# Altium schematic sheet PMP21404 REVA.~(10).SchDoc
size 431 x 279 mm; Date: Not shown in title block; ApprovedBy: Not shown in title block; CheckedBy: Not shown in title block; Author: Not shown in title block; CompanyName: Not shown in title block; Engineer: Not shown in title block; Organization: Not shown in title block; Address1: Not shown in title block; Address2: Not shown in title block; Address3: Not shown in title block; Address4: Not shown in title block; DocumentNumber: 1; Revision: Use project parameter SCH_Rev; SheetNumber: 1; SheetTotal: 1; PageSetup: Record=PageOptions¦CenterHorizontal=True¦CenterVertical=True¦PrintScale=1.00¦XCorrection=1.00¦YCorrection=1.00¦PrintKind=0¦BorderSize=5000000¦LeftOffset=0¦BottomOffset=0¦Orientation=2¦PaperLength=1000¦PaperWidth=1000¦Scale=100¦PaperSource=15¦PrintQuality=600¦MediaType=1¦DitherType=10¦PaperKind=Letter¦PrintScaleMode=1
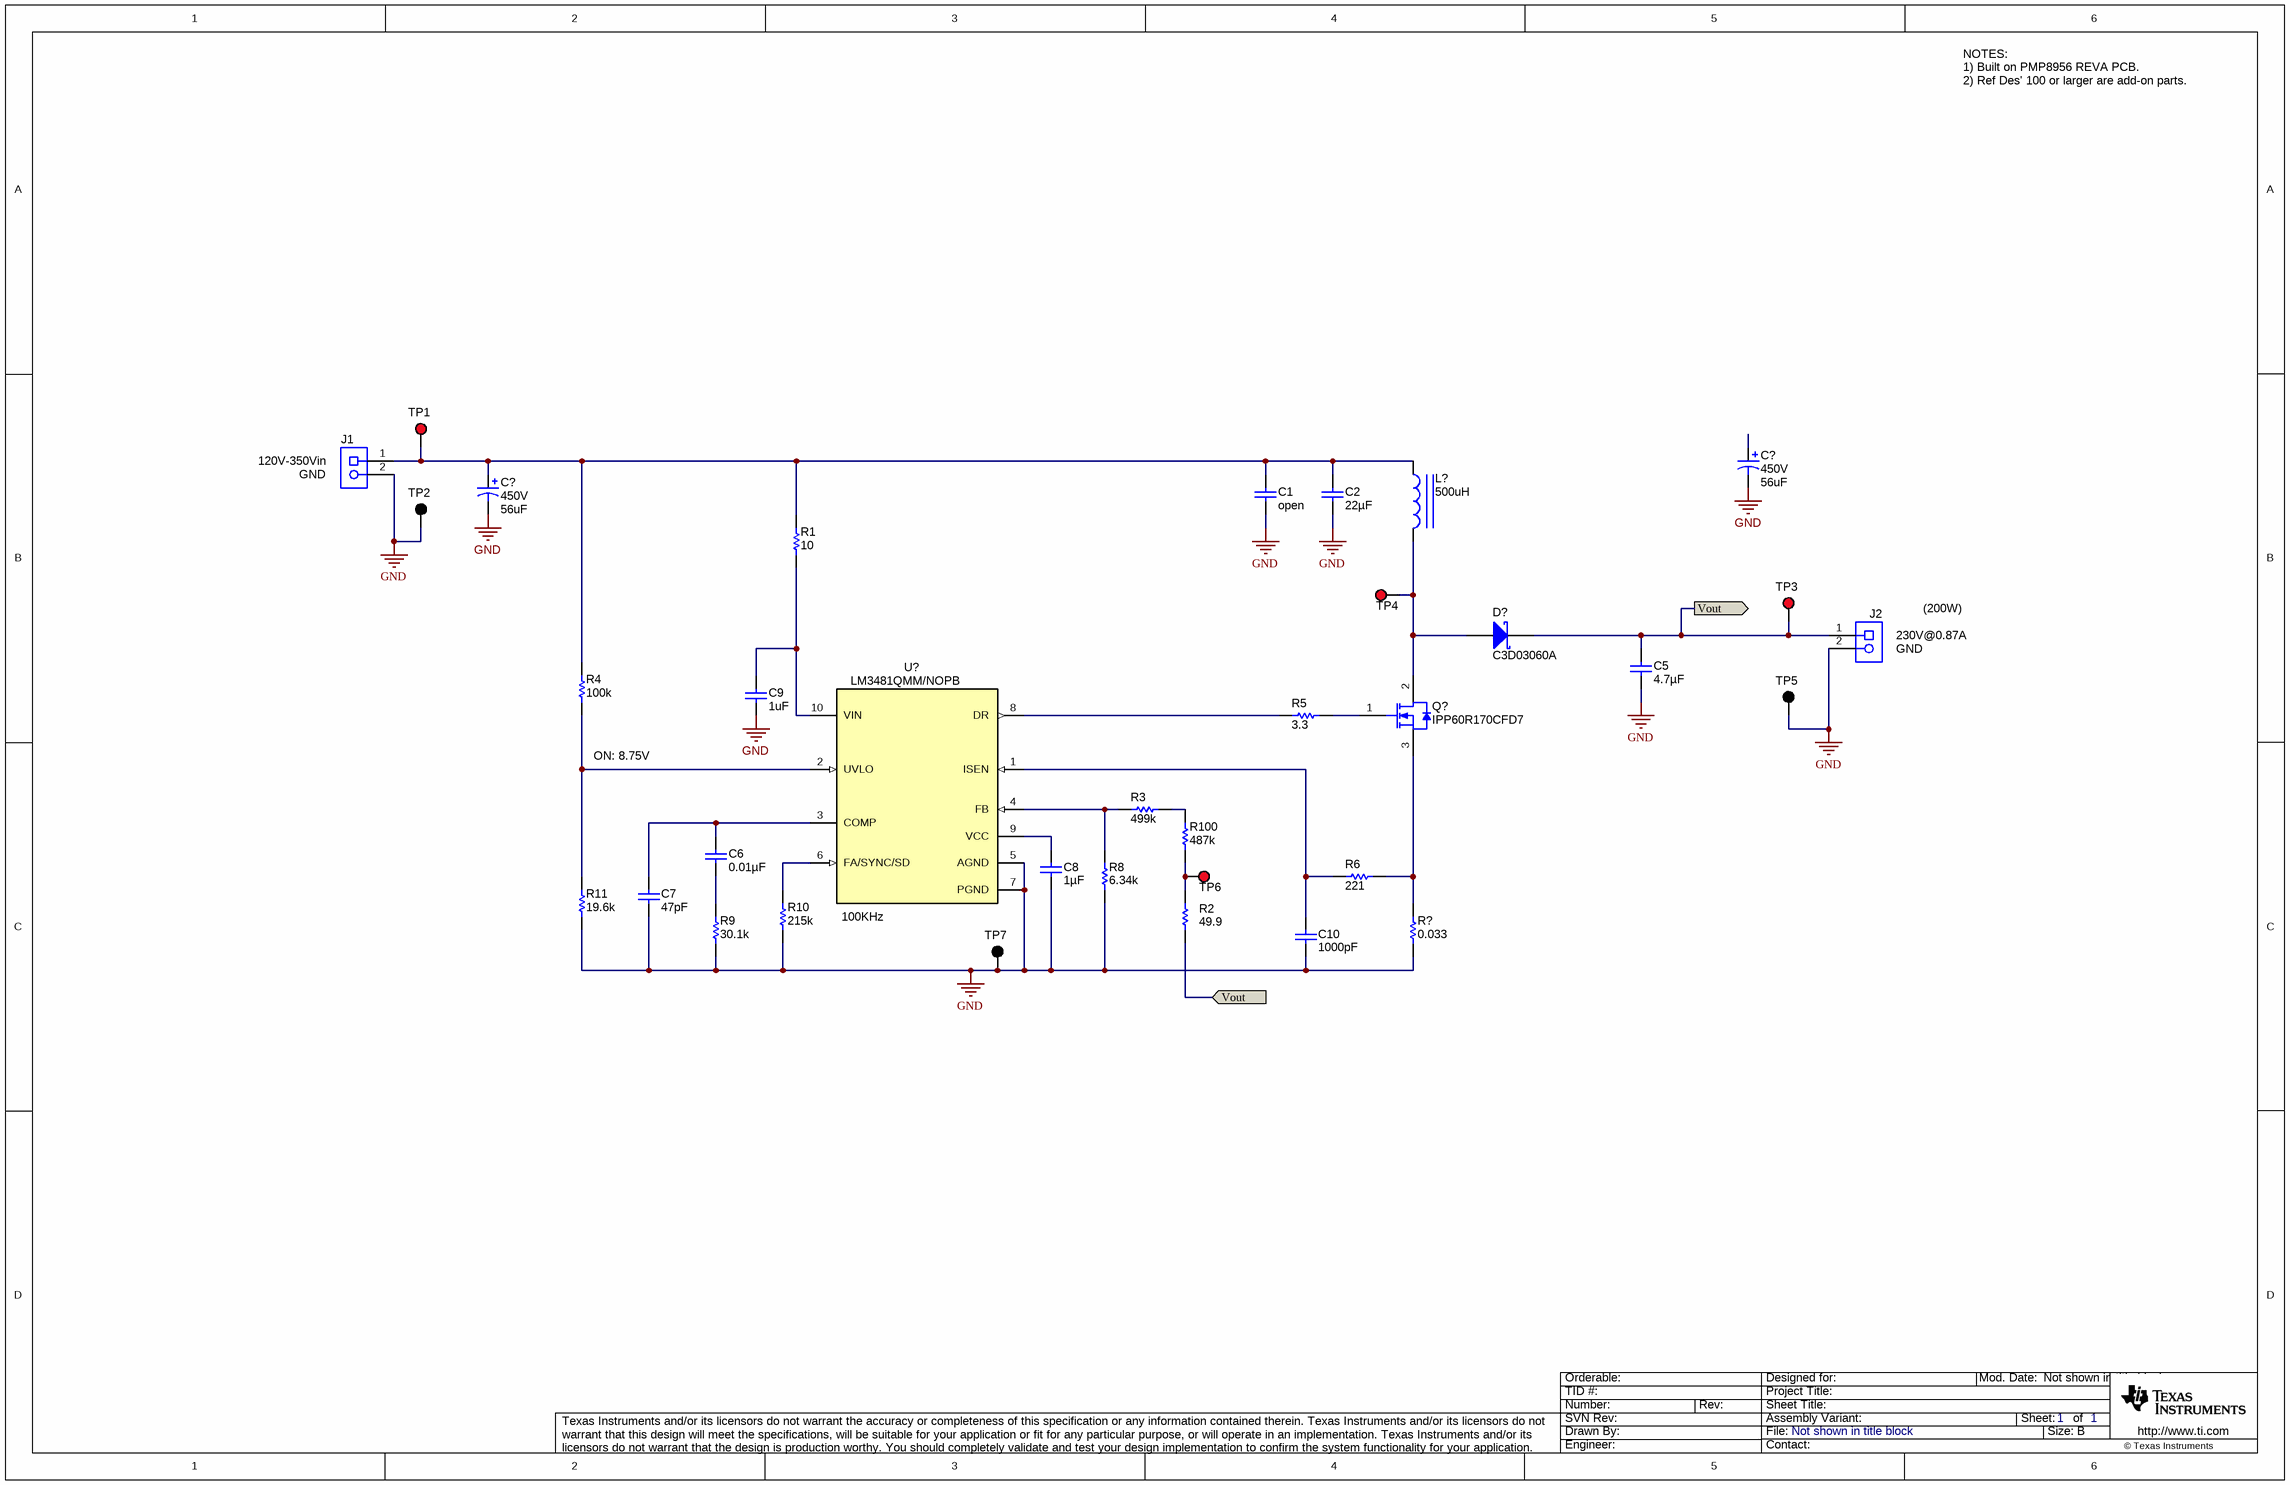
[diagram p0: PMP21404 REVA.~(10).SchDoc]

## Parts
(Parts that share a designator on the sheet are numbered #1, #2 ... from top to bottom, then left to right.)
C1  ValueDisplayed: open  [1206L]
C2  ValueDisplayed: 22µF  [1210]  (hidden comment: GRM32ER71E226ME15)
C5  ValueDisplayed: 4.7µF  [1210]  (hidden comment: C3225X7S2A475M)
C6  ValueDisplayed: 0.01µF  [0603]  (hidden comment: C1608X7R1H103K)
C7  ValueDisplayed: 47pF  [0603]  (hidden comment: C1608C0G1H470J)
C8  ValueDisplayed: 1µF  [0603L]  (hidden comment: C1608X7R1C105K)
C9  ValueDisplayed: 1uF  [0805L]  (hidden comment: Capacitor)
C10  ValueDisplayed: 1000pF  [0603L]  (hidden comment: C1608X7R1H102K)
C?#1  VDC_V: 450V  ValueDisplayed: 56uF  [Nichicon_2000x2500_Snap]  (hidden comment: LLS2W560MELY)
C?#2  VDC_V: 450V  ValueDisplayed: 56uF  [Nichicon_2000x2500_Snap]  (hidden comment: LLS2W560MELY)
D?  C3D03060A  [TO-220-2]
J1  Receptacle_2x1  [TERM_BLK_ED555-2DS]  (value not drawn)
J2  Receptacle_2x1  [TERM_BLK_ED555-2DS]  (value not drawn)
L?  ValueDisplayed: 500uH  [5717-RC]  (hidden comment: 5717-RC)
Q?  IPP60R170CFD7  [TO-220AB]
R1  value 10  [0603L]  (hidden comment: Resistor)
R2  value 49.9  [0603L]  (hidden comment: Resistor)
R3  ValueDisplayed: 499k  [0805_HV]  (hidden comment: Resistor)
R4  value 100k  [0603L]  (hidden comment: Resistor)
R5  ValueDisplayed: 3.3  [0603]  (hidden comment: Resistor)
R6  value 221  [0603L]  (hidden comment: Resistor)
R8  ValueDisplayed: 6.34k  [0603L]  (hidden comment: Resistor)
R9  ValueDisplayed: 30.1k  [0603]  (hidden comment: Resistor)
R10  value 215k  [0603]  (hidden comment: Resistor)
R11  value 19.6k  [0603L]  (hidden comment: Resistor)
R100  ValueDisplayed: 487k  [0805_HV]  (hidden comment: Resistor)
R?  ValueDisplayed: 0.033  [1206]  (hidden comment: ERJ-8CWFR033V)
TP1  5000  [Keystone5000]  (value not drawn)
TP2  5001  [Keystone5001]  (value not drawn)
TP3  5000  [Keystone5000]  (value not drawn)
TP4  5000  [Keystone5000]  (value not drawn)
TP5  5001  [Keystone5001]  (value not drawn)
TP6  5000  [Keystone5000]  (value not drawn)
TP7  5001  [Keystone5001]  (value not drawn)
U?  LM3481QMM/NOPB  [DGS0010A_N]

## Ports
Vout

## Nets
GND: C1.2 C2.2 C5.2 C7.2 C8.2 C9.2 C10.2 C?#1.2(-) C?#2.2(-) J1.2 J2.2 R8.1 R9.1 R10.1 R11.1 R?.1 TP2.1 TP5.1 TP7.1 U?.5(AGND) U?.7(PGND)
Vout: C5.1 D?.1(K) J2.1 R2.1 TP3.1 ; port Vout
NetC1_1: C1.1 C2.1 C?#2.1(+) J1.1 L?.1 R1.2 R4.2 TP1.1
NetC6_1: C6.1 C7.1 U?.3(COMP)
NetC6_2: C6.2 R9.2
NetC8_1: C8.1 U?.9(VCC)
NetC9_1: C9.1 R1.1 U?.10(VIN)
NetC10_1: C10.1 R6.2 U?.1(ISEN)
NetD?_2: D?.2(A) L?.2 Q?.2(D) TP4.1
NetQ?_1: Q?.1(G) R5.2
NetQ?_3: Q?.3(S) R6.1 R?.2
NetR2_2: R2.2 R100.1 TP6.1
NetR3_1: R3.1 R8.2 U?.4(FB)
NetR3_2: R3.2 R100.2
NetR4_1: R4.1 R11.2 U?.2(UVLO)
NetR5_1: R5.1 U?.8(DR)
NetR10_2: R10.2 U?.6(FA/SYNC/SD)

Not connected (* = marked no-connect by the designer): C?#1 1(+)

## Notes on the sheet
- NOTES:
  1) Built on PMP8956 REVA PCB.
  2) Ref Des' 100 or larger are add-on parts.
- (near J1) 120V-350Vin
- (near J1) GND
- (near J2) 230V@0.87A
- (200W)
- (near J2) GND
- (near R4) ON: 8.75V
- (near U?) 100KHz

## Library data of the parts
C1 = C3216X7R2A104M: CAP, open, 1206; Polarized: N; CompType: Capacitor; U/M: EA; Cap_F: 0.0000001; Tolerance_%: 20; TaMin_C: -55; TaMax_C: 125
C2 = GRM32ER71E226KE15L: CAP, CERM, 22 µF, 25 V, +/- 10%, X7R, 1210; Manufacturer: MuRata; Polarized: N; CompType: Capacitor; Value: 22uF; U/M: EA; Cap_F: 0.000022; Tolerance_%: 10; Value1: Unknown; VDC_V: 25; Value2: 25V; TaMin_C: -55; TaMax_C: 125; AEC Category: Q200
C5 = C3225X5R1E106K: CAP, CERM, 4.7uF, 100V, +/-20%, X7S, 1210; Manufacturer: TDK; Polarized: N; CompType: Capacitor; U/M: EA; Cap_F: 0.00001; Tolerance_%: 20; ESR_Ohm: 0.015; Value1: 0.015 ohm; VDC_V: 100; IRMS_A: 3; TaMin_C: -55; TaMax_C: 125
C6 = C1608X7R1H103K: CAP, CERM, 0.01uF, 50V, +/-10%, X7R, 0603; Manufacturer: TDK; Polarized: N; CompType: Capacitor; U/M: EA; Cap_F: 0.00000001; Tolerance_%: 10; ESR_Ohm: 0.0539; Value1: 0.0539 ohm; VDC_V: 50; TaMin_C: -55; TaMax_C: 125
C7 = C1608C0G1H470J: CAP, CERM, 47pF, 50V, +/-5%, C0G/NP0, 0603; Manufacturer: TDK; Polarized: N; CompType: Capacitor; U/M: EA; Cap_F: 0.000000000047; Tolerance_%: 5; ESR_Ohm: 0.22; Value1: 0.22 ohm; VDC_V: 50; TaMin_C: -55; TaMax_C: 125
C8 = C1608X7R1C105K: CAP, CERM, 1uF, 16V, +/-10%, X7R, 0603; Manufacturer: TDK; Polarized: N; CompType: Capacitor; U/M: EA; Cap_F: 0.000001; Tolerance_%: 10; ESR_Ohm: 0.0057; Value1: 0.0057 ohm; VDC_V: 16; TaMin_C: -55; TaMax_C: 125; Cap_Case: 0603
C9 = CMP-0008350-2: CAP, CERM, 1 uF, 50 V, +/- 10%, X7R, 0805; PartNumber: GRM21BR71H105KA12L; Manufacturer: MuRata; Polarized: N; Value: 1uF; U/M: EA; Cap_F: 1µF; Value1: Unknown; VDC_V: 50V; TaMin_C: -55°C; TaMax_C: 125°C; Cap_Case: 0805; AEC Category: Q200; SizeArea_mm2: 2.5; SizeAreaWB_mm2: 6.75; SizeX_mm: 2; SizeY_mm: 1.25; SizeZ_mm: 1.45
C10 = C1608X7R1H102K: CAP, CERM, 1000pF, 50V, +/-10%, X7R, 0603; Manufacturer: TDK; Polarized: N; CompType: Capacitor; U/M: EA; Cap_F: 0.000000001; Tolerance_%: 10; ESR_Ohm: 0.24; Value1: 0.24 ohm; VDC_V: 50; TaMin_C: -55; TaMax_C: 125; Cap_Case: 0603
C?#1 C?#2 = CMP-0010119-2: CAP, AL, 56 uF, 450 V, +/- 20%, TH; Manufacturer: Nichicon; TaMin_C: -25°C; Polarized: Y; SizeAreaWB_mm2: 484; Value1: Unknown; U/M: EA; Value: 56uF; TaMax_C: 85°C; SizeZ_mm: 27; SizeX_mm: 20; Cap_Case: 20x25mm; SizeArea_mm2: 400; CompType: Capacitor; AEC Qualified: N; Cap_F: 56µF; IRMS_A: 6.1dA; AEC Category: Q200
D? = CMP-0079543-1: Diode, Schottky, 600 V, 11 A, AEC-Q101, TH; Manufacturer: Cree; SizeAreaWB_mm2: 77.630025; Vr_V: 600V; SizeArea_mm2: 44.650025; AEC Qualified: Y; TJmax_C: 175°C; AEC Category: Q101; Value: 600V; SizeZ_mm: 20; Green_REACh: Incomplete; Io_A: 11A; SizeY_mm: 4.445; Green_Lifecycle: Active; SizeX_mm: 10.045; RJC_CperW: 3.2
J1 J2 = CMP-0074913-1: Terminal Block, 3.5mm Pitch, 2x1, TH; PartNumber: ED555/2DS; Manufacturer: On-Shore Technology; Cert_CULUS: Y; CNHeader: False; ContactFinish: Brass; CT: True; Current_A: 6A; Gender: Female; Green_Lifecycle: Active; Green_REACh: Passed; Pitch_mm: 3.5; Row_Count: 1; Shrouded: N; Voltage_V: 150V
L? = CMP-0055726-1: Inductor, Toroid, Powdered Iron, 500 uH, 4 A, 0.15 ohm, TH; Manufacturer: Bourns; SizeAreaWB_mm2: 1008; DCR_ohm: 1.5d; Value: 500uH; Imax_A: 4A; SizeZ_mm: 46; SizeX_mm: 19; SizeArea_mm2: 874; Ind_H: 500µH; AEC Qualified: N; AEC Category: Q200
Q? = CMP-0001174-3: MOSFET, N-CH, 600 V, 51 A, TO-220AB; Alternate Manufacturer: None; Manufacturer: Infineon Technologies; SizeZ_mm: 19.4; ChType: N; Value2: 28 nC; VdsMax_V: 600V; SizeX_mm: 10.2; SizeY_mm: 4.5; Vgs_V: 20V; Value: 600V; SizeArea_mm2: 45.9; AEC Category: Q101; IdsMax_A: 51A; SizeAreaWB_mm2: 79.3; U/M: EA; QgTyp_nC: 28
R1 = CMP-0025703-4: RES, 10, 5%, 0.1 W, AEC-Q200 Grade 0, 0603; PartNumber: CRCW060310R0JNEA; Manufacturer: Vishay-Dale; Value_Code: 10R0; Power_W: 100mW; Value2: 0.1W; VDC_V: 75V; TempCo: 200 ppm/C; EIA_Code: E24; AEC Category: Q200; AEC Grade: 0; AEC Qualified: Y; SizeArea_mm2: 1.28; SizeX_mm: 1.6; SizeY_mm: 0.8; SizeZ_mm: 1
R2 = CMP-0022448-4: RES, 49.9, 1%, 0.1 W, AEC-Q200 Grade 0, 0603; PartNumber: CRCW060349R9FKEA; Manufacturer: Vishay-Dale; Value_Code: 49R9; Power_W: 100mW; Value2: 0.1W; VDC_V: 75V; TempCo: 100 ppm/C; EIA_Code: E96; AEC Category: Q200; AEC Grade: 0; AEC Qualified: Y; SizeArea_mm2: 1.28; SizeX_mm: 1.6; SizeY_mm: 0.8; SizeZ_mm: 1
R3 = CMP-0021281-3: RES, 499 k, 1%, 0.125 W, AEC-Q200 Grade 0, 0805; PartNumber: CRCW0805499KFKEA; Manufacturer: Vishay-Dale; Value: 499k; Power_W: 125mW; Value2: 0.125W; VDC_V: 150V; TempCo: 100 ppm/C; EIA_Code: E96; AEC Category: Q200; AEC Qualified: Y; AEC Grade: 0; SizeArea_mm2: 2.5; SizeX_mm: 2; SizeY_mm: 1.25; SizeZ_mm: 1.45
R4 = CMP-0021990-4: RES, 100 k, 1%, 0.1 W, AEC-Q200 Grade 0, 0603; PartNumber: CRCW0603100KFKEA; Manufacturer: Vishay-Dale; Power_W: 100mW; Value2: 0.1W; VDC_V: 75V; TempCo: 100 ppm/C; EIA_Code: E96; AEC Category: Q200; AEC Grade: 0; AEC Qualified: Y; SizeArea_mm2: 1.28; SizeX_mm: 1.6; SizeY_mm: 0.8; SizeZ_mm: 1
R5 = CMP-0025805-4: RES, 3.3, 5%, 0.1 W, AEC-Q200 Grade 0, 0603; PartNumber: CRCW06033R30JNEA; Manufacturer: Vishay-Dale; Value: 3.3; Value_Code: 3R30; Power_W: 100mW; Value2: 0.1W; VDC_V: 75V; TempCo: 200 ppm/C; EIA_Code: E24; AEC Category: Q200; AEC Qualified: Y; AEC Grade: 0; SizeArea_mm2: 1.28; SizeX_mm: 1.6; SizeY_mm: 0.8; SizeZ_mm: 1
R6 = CMP-0022217-5: RES, 221, 1%, 0.1 W, AEC-Q200 Grade 0, 0603; PartNumber: CRCW0603221RFKEA; Manufacturer: Vishay-Dale; Value_Code: 221R; Power_W: 100mW; Value2: 0.1W; VDC_V: 75V; TempCo: 100 ppm/C; EIA_Code: E96; AEC Category: Q200; AEC Grade: 0; AEC Qualified: Y; SizeArea_mm2: 1.28; SizeX_mm: 1.6; SizeY_mm: 0.8; SizeZ_mm: 1
R8 = CMP-0022560-4: RES, 6.34 k, 1%, 0.1 W, AEC-Q200 Grade 0, 0603; PartNumber: CRCW06036K34FKEA; Manufacturer: Vishay-Dale; Value: 6.34k; Value_Code: 6k34; Power_W: 100mW; Value2: 0.1W; VDC_V: 75V; TempCo: 100 ppm/C; EIA_Code: E96; AEC Category: Q200; AEC Qualified: Y; AEC Grade: 0; SizeArea_mm2: 1.28; SizeX_mm: 1.6; SizeY_mm: 0.8; SizeZ_mm: 1
R9 = CMP-0022324-4: RES, 30.1 k, 1%, 0.1 W, AEC-Q200 Grade 0, 0603; PartNumber: CRCW060330K1FKEA; Manufacturer: Vishay-Dale; Value: 30.1k; Value_Code: 30k1; Power_W: 100mW; Value2: 0.1W; VDC_V: 75V; TempCo: 100 ppm/C; EIA_Code: E96; AEC Category: Q200; AEC Qualified: Y; AEC Grade: 0; SizeArea_mm2: 1.28; SizeX_mm: 1.6; SizeY_mm: 0.8; SizeZ_mm: 1
R10 = CMP-0022210-4: RES, 215 k, 1%, 0.1 W, AEC-Q200 Grade 0, 0603; PartNumber: CRCW0603215KFKEA; Manufacturer: Vishay-Dale; Power_W: 100mW; Value2: 0.1W; VDC_V: 75V; TempCo: 100 ppm/C; EIA_Code: E96; AEC Category: Q200; AEC Grade: 0; AEC Qualified: Y; SizeArea_mm2: 1.28; SizeX_mm: 1.6; SizeY_mm: 0.8; SizeZ_mm: 1
R11 = CMP-0022106-4: RES, 19.6 k, 1%, 0.1 W, AEC-Q200 Grade 0, 0603; PartNumber: CRCW060319K6FKEA; Manufacturer: Vishay-Dale; Value_Code: 19k6; Power_W: 100mW; Value2: 0.1W; VDC_V: 75V; TempCo: 100 ppm/C; EIA_Code: E96; AEC Category: Q200; AEC Grade: 0; AEC Qualified: Y; SizeArea_mm2: 1.28; SizeX_mm: 1.6; SizeY_mm: 0.8; SizeZ_mm: 1
R100 = CMP-0021277-3: RES, 487 k, 1%, 0.125 W, AEC-Q200 Grade 0, 0805; PartNumber: CRCW0805487KFKEA; Manufacturer: Vishay-Dale; Value: 487k; Power_W: 125mW; Value2: 0.125W; VDC_V: 150V; TempCo: 100 ppm/C; EIA_Code: E96; AEC Category: Q200; AEC Qualified: Y; AEC Grade: 0; SizeArea_mm2: 2.5; SizeX_mm: 2; SizeY_mm: 1.25; SizeZ_mm: 1.45
R? = CMP-0017280-2: RES, 0.033, 1%, 1 W, AEC-Q200 Grade 0, 1206; Manufacturer: Panasonic; Power_W: 1W; TempCo: 50 ppm/C; Value_Code: R033; U/M: EA; Value: 0.033; EIA_Code: E96; SizeX_mm: 3.2; SizeY_mm: 1.6; SizeZ_mm: 1.35; SizeArea_mm2: 5.12; AEC Qualified: Y; AEC Grade: 0; AEC Category: Q200
TP1 TP3 TP4 TP6 = CMP-0055137-1: Test Point, Miniature, Red, TH; Manufacturer: Keystone; CNHeader: FALSE; ContactFinish: Silver; CT: TRUE; Green_Lifecycle: Active; Green_REACh: Passed
TP2 TP5 TP7 = CMP-0055138-1: Test Point, Miniature, Black, TH; Manufacturer: Keystone; CNHeader: FALSE; ContactFinish: Silver; CT: TRUE; Green_Lifecycle: Active; Green_REACh: Passed
U? = CMP-0071928-2: High Efficiency Low-Side N-Channel Controller for Switching Regulators, AEC-Q100 Grade 1, 10-pin Mini SOIC, 1000 Reel; Manufacturer: Texas Instruments; Alternate PartNumber: LM3481QMMX/NOPB; CompType: IC; AEC Category: Q200; AEC Qualified: Y; SizeAreaWB_mm2: 23.6; SizeArea_mm2: 14.7; SizeX_mm: 4.9; SizeY_mm: 3; SizeZ_mm: 1.1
